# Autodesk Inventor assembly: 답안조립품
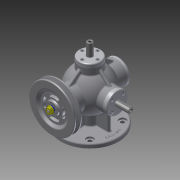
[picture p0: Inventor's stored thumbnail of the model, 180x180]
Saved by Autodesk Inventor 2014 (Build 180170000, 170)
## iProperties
Created: 2016-07
Part Number: 답안조립품
Document SubType Name: Assembly
Designer: owner
Author: owner
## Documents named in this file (17)
- C:\Users\owner\Desktop\360707V1016\답안조립품.iam
- C:\Users\owner\Desktop\360707V1016\본체.ipt
- C:\Users\owner\Desktop\360707V1016\V-벨트풀리.ipt
- C:\Users\owner\Desktop\360707V1016\너트-M8x1.ipt
- C:\Users\owner\Desktop\360707V1016\뒤커버.ipt
- C:\Users\owner\Desktop\360707V1016\베어링- 6202.ipt
- C:\Users\owner\Desktop\360707V1016\본체커버.ipt
- C:\Users\owner\Desktop\360707V1016\볼트 M4x0.7.ipt
- C:\Users\owner\Desktop\360707V1016\스프링1.ipt
- C:\Users\owner\Desktop\360707V1016\스프링2.ipt
- C:\Users\owner\Desktop\360707V1016\슬라이드 커버.ipt
- C:\Users\owner\Desktop\360707V1016\슬라이드.ipt
- C:\Users\owner\Desktop\360707V1016\앞커버.ipt
- C:\Users\owner\Desktop\360707V1016\오일실.ipt
- C:\Users\owner\Desktop\360707V1016\와셔 8x17.ipt
- C:\Users\owner\Desktop\360707V1016\축.ipt
- C:\Users\owner\Desktop\360707V1016\키-4x4.ipt
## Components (18 placed, 2 different names)
1. V-벨트풀리:1
2. M4x0.7x12:1 — 각도:1
3. M4x0.7x12:3 — 각도:2
4. M4x0.7x12:4
5. M4x0.7x12:5
6. M4x0.7x12:6
7. M4x0.7x12:7 — 각도:3
8. M4x0.7x12:8
9. M4x0.7x12:9
10. M4x0.7x12:10
11. M4x0.7x12:2
12. M4x0.7x12:11
13. M4x0.7x12:12
14. M4x0.7x12:13
15. M4x0.7x12:14 — 각도:6
16. M4x0.7x12:15
17. M4x0.7x12:16
18. M4x0.7x12:17
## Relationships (4: Angle 4)
- 각도:1 [Angle]: M4x0.7x12:1
- 각도:2 [Angle]: M4x0.7x12:3
- 각도:3 [Angle]: M4x0.7x12:7
- 각도:6 [Angle]: M4x0.7x12:14
